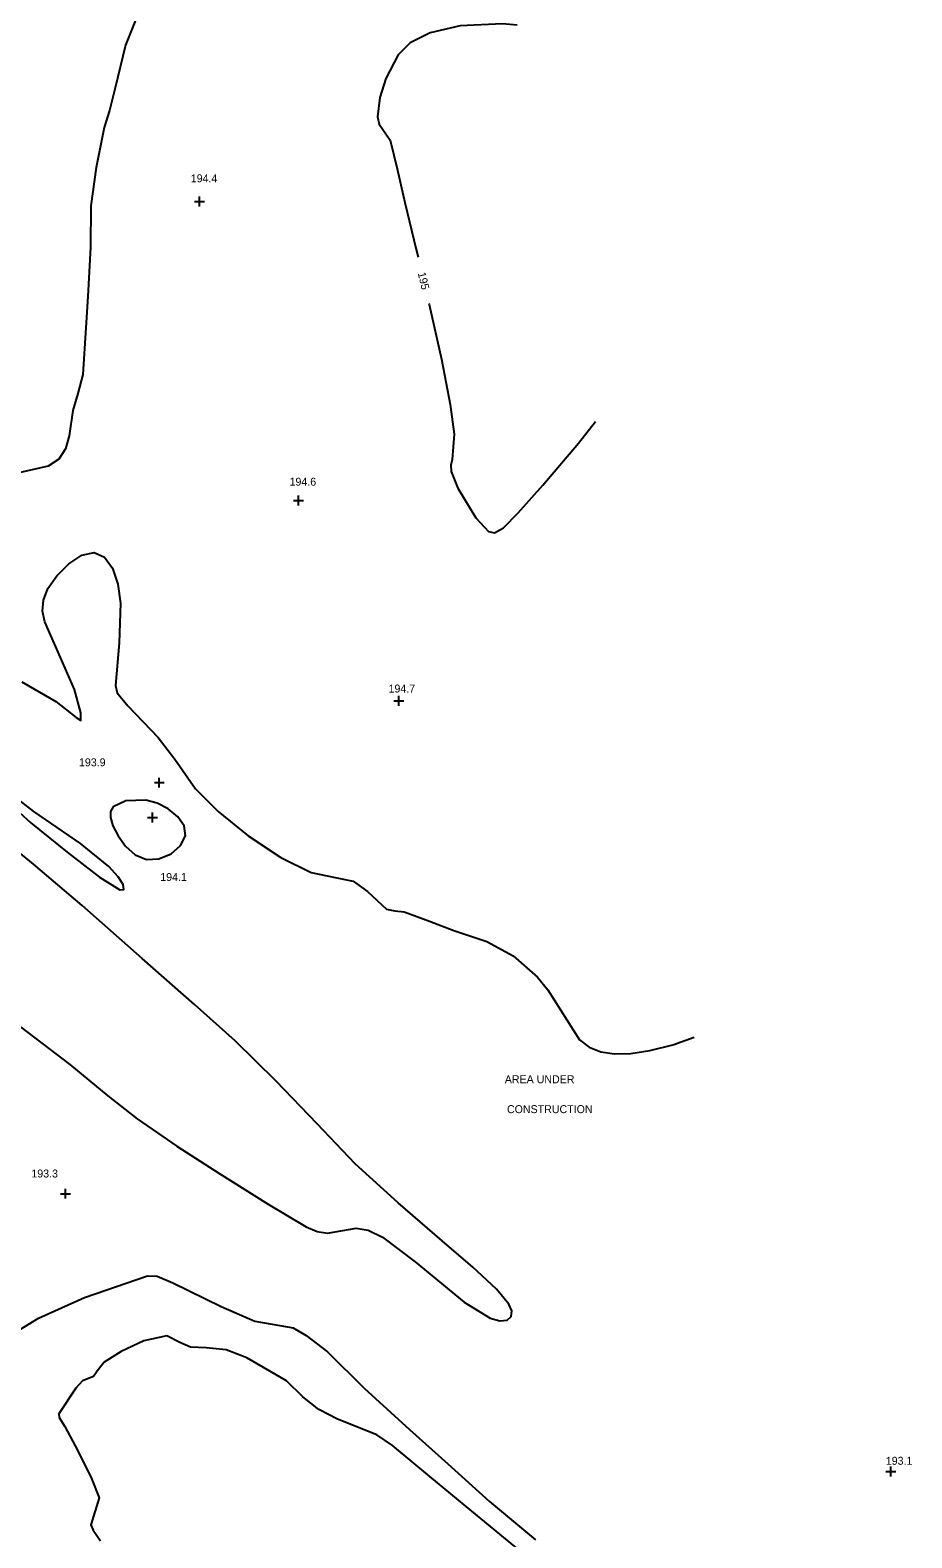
# Model space of a CAD drawing. Extents: x 1467615 to 2003689, y 770235 to 1108726.
# Drawn here: x 1993657.3 to 1993879.2, y 778214.1 to 778593.3 of the extents above; entities that cross this region are included whole.
import ezdxf

# ---------------------------------------------------------------- set-up
doc = ezdxf.new("R2010")
doc.units = 0
for name, color, linetype in [('RD_DTM_Major1', 7, 'Continuous'), ('RD_DTM_Major1_Lbl', 7, 'Continuous'), ('RD_DTM_Minor1', 7, 'Continuous'), ('RD_DTM_Spot_Elev', 7, 'Continuous'), ('RD_TX_Misc1', 7, 'Continuous')]:
    doc.layers.add(name, color=color, linetype=linetype)

msp = doc.modelspace()

# ---------------------------------------------------------------- linework, layer by layer
at = {"layer": 'RD_DTM_Major1'}
for points in [[(1993779.86, 778594.54), (1993776.19, 778594.9), (1993765.56, 778594.4), (1993757.94, 778592.66), (1993752.98, 778590.1), (1993749.94, 778587.08), (1993746.82, 778581.13), (1993745.34, 778576.33), (1993744.74, 778571.51), (1993745.18, 778569.67), (1993747.91, 778565.66), (1993749.72, 778558.11), (1993751.63, 778549.96), (1993754.47, 778538.13), (1993754.92, 778536.19)], [(1993757.68, 778524.51), (1993757.74, 778524.27), (1993760.81, 778510.55), (1993763.04, 778499.16), (1993763.98, 778491.69), (1993763.52, 778485.31), (1993763.14, 778483.92), (1993763.27, 778482.3), (1993764.93, 778478.06), (1993769.47, 778470.62), (1993772.68, 778467.23), (1993774.2, 778466.85), (1993776.39, 778468.15), (1993780.13, 778471.89), (1993786.31, 778478.82), (1993795.32, 778489.39), (1993799.58, 778494.88)]]:
    msp.add_lwpolyline(points, dxfattribs=at)
at = {"layer": 'RD_DTM_Minor1'}
for points in [[(1993685.52, 778600), (1993681.34, 778589.53), (1993678.67, 778578.77), (1993677.25, 778573.12), (1993675.97, 778568.85), (1993673.95, 778558.76), (1993672.6, 778549.14), (1993672.46, 778538.75), (1993671.85, 778526.28), (1993671.3, 778518.42), (1993670.59, 778506.67), (1993669.31, 778501.92), (1993668.03, 778497.65), (1993667.11, 778491.27), (1993666.18, 778488.01), (1993664.49, 778485.37), (1993661.81, 778483.66), (1993654.44, 778481.97)], [(1993655.18, 778429.35), (1993663.81, 778424.4), (1993668.9, 778420.37), (1993670.06, 778419.66), (1993670.06, 778421.56), (1993668.5, 778427.46), (1993664.95, 778435.51), (1993661.02, 778444.49), (1993660.46, 778447.16), (1993660.64, 778449.88), (1993661.79, 778452.83), (1993664.03, 778456.04), (1993667.01, 778459.04), (1993670.29, 778461.21), (1993673.43, 778461.92), (1993676.05, 778460.74), (1993678.05, 778457.93), (1993679.41, 778453.93), (1993680.09, 778449.19), (1993679.72, 778439.17), (1993678.76, 778428.46), (1993679.24, 778426.65), (1993681.93, 778423.38), (1993689.51, 778415.4), (1993693.74, 778409.91), (1993698.88, 778402.48), (1993704.64, 778396.74), (1993712.18, 778390.68), (1993720.42, 778385.15), (1993728.07, 778381.42), (1993734.07, 778380.15), (1993738.63, 778379.22), (1993742.21, 778376.64), (1993747.02, 778372.19), (1993749.07, 778371.77), (1993751.45, 778371.54), (1993757.8, 778369.15), (1993763.91, 778366.84), (1993772.26, 778364.08), (1993778.84, 778360.44), (1993784.97, 778355.06), (1993787.56, 778351.87), (1993795.57, 778339.35), (1993798, 778337.47), (1993800.91, 778336.3), (1993804.37, 778335.8), (1993808.47, 778335.91), (1993813.29, 778336.61), (1993819.02, 778338.07), (1993824.39, 778339.96)], [(1993648.98, 778401.57), (1993657.5, 778393.87), (1993666.61, 778386.57), (1993674.74, 778380.27), (1993679.87, 778377.09), (1993680.9, 778377.18), (1993680.73, 778378.36), (1993679.44, 778380.37), (1993677.09, 778382.93), (1993670.01, 778388.7), (1993658.28, 778396.73), (1993652.97, 778400.9)], [(1993689.24, 778398.86), (1993686.39, 778399.61), (1993681.36, 778399.47), (1993678.18, 778397.96), (1993677.53, 778396.78), (1993677.51, 778395.22), (1993678.15, 778393.16), (1993679.44, 778390.62), (1993681.31, 778388.01), (1993683.71, 778385.86), (1993686.57, 778384.68), (1993689.73, 778384.85), (1993692.77, 778386.14), (1993695.16, 778388.2), (1993696.37, 778390.64), (1993696.05, 778393.13), (1993694.48, 778395.46), (1993692.06, 778397.43), (1993689.24, 778398.86)], [(1993654.99, 778342.55), (1993667.32, 778333.15), (1993676.83, 778325.2), (1993684.22, 778319.44), (1993694.26, 778312.57), (1993704.81, 778305.77), (1993717.17, 778297.96), (1993726.74, 778292.26), (1993729.53, 778291.12), (1993732.1, 778290.68), (1993739.38, 778291.94), (1993742.37, 778291.44), (1993745.94, 778289.68), (1993754.21, 778283.5), (1993766.51, 778273.38), (1993773.06, 778269.31), (1993775.54, 778268.64), (1993777.36, 778268.83), (1993778.39, 778269.72), (1993778.53, 778271.12), (1993777.74, 778272.87), (1993774.65, 778276.59), (1993768.69, 778282.12), (1993761.01, 778288.75), (1993749.96, 778298.36), (1993739.14, 778308.15), (1993729.58, 778318.17), (1993719.21, 778328.93), (1993708.87, 778339.05), (1993698.67, 778348.24), (1993685.53, 778359.81), (1993670.39, 778373.1), (1993658.18, 778383.53), (1993646.2, 778393.24)], [(1993652.04, 778264.81), (1993659.45, 778269.28), (1993671.01, 778274.49), (1993686.81, 778279.98), (1993689.24, 778279.86), (1993693.2, 778278.18), (1993705.35, 778272.24), (1993713.86, 778268.54), (1993718.25, 778267.82), (1993723.5, 778266.9), (1993726.74, 778264.95), (1993732.11, 778260.87), (1993741.38, 778251.74), (1993752.74, 778241.29), (1993762.41, 778232.66), (1993772.92, 778223.2), (1993784.44, 778213.56)], [(1993781.65, 778209.93), (1993768.47, 778220.74), (1993757.89, 778229.52), (1993748.48, 778237.29), (1993744.55, 778240.01), (1993734.69, 778243.87), (1993729.93, 778246.32), (1993725.92, 778249.55), (1993721.85, 778253.58), (1993711.84, 778259.37), (1993706.62, 778261.37), (1993701.61, 778261.82), (1993697.66, 778262), (1993694.95, 778263.23), (1993691.73, 778264.84), (1993685.96, 778263.63), (1993680.22, 778260.93), (1993675.95, 778258.22), (1993674.18, 778256), (1993673.23, 778254.67), (1993670.47, 778253.52), (1993668.77, 778251.72), (1993664.55, 778245.29), (1993664.64, 778244.32), (1993666.06, 778242.08), (1993669.3, 778235.95), (1993672.79, 778228.99), (1993674.71, 778224.14), (1993672.59, 778217.35), (1993673.2, 778215.99), (1993675.02, 778213.32)]]:
    msp.add_lwpolyline(points, dxfattribs=at)
at = {"layer": 'RD_DTM_Spot_Elev'}
for p, q in [((1993699.91, 778548.98), (1993699.91, 778551.48)), ((1993698.66, 778550.23), (1993701.16, 778550.23)), ((1993724.85, 778473.77), (1993724.85, 778476.27)), ((1993723.6, 778475.02), (1993726.1, 778475.02)), ((1993748.87, 778424.58), (1993751.37, 778424.58)), ((1993750.12, 778423.33), (1993750.12, 778425.83)), ((1993688.57, 778404.02), (1993691.07, 778404.02)), ((1993689.82, 778402.77), (1993689.82, 778405.27)), ((1993688.1, 778393.97), (1993688.1, 778396.47)), ((1993686.85, 778395.22), (1993689.35, 778395.22)), ((1993666.19, 778299.38), (1993666.19, 778301.88)), ((1993664.94, 778300.63), (1993667.44, 778300.63)), ((1993872.68, 778230.72), (1993875.18, 778230.72)), ((1993873.93, 778229.47), (1993873.93, 778231.97))]:
    msp.add_line(p, q, dxfattribs=at)

# ---------------------------------------------------------------- texts
at = {"layer": 'RD_DTM_Major1_Lbl'}
msp.add_text('195', height=2, rotation=283.2829, dxfattribs=at).set_placement((1993754.84, 778532.19))
at = {"layer": 'RD_DTM_Spot_Elev'}
for s, p in [('194.4', (1993697.73, 778555.03)), ('194.6', (1993722.59, 778478.72)), ('194.7', (1993747.5, 778426.69)), ('193.9', (1993669.6, 778408.13)), ('194.1', (1993690.05, 778379.28)), ('193.3', (1993657.62, 778304.7)), ('193.1', (1993872.63, 778232.44))]:
    msp.add_text(s, height=2, dxfattribs=at).set_placement(p)
at = {"layer": 'RD_TX_Misc1'}
for s, p in [('AREA UNDER', (1993776.75, 778328.41)), ('CONSTRUCTION', (1993777.3, 778320.89))]:
    msp.add_text(s, height=2, dxfattribs=at).set_placement(p)

doc.saveas('drawing.dxf')
